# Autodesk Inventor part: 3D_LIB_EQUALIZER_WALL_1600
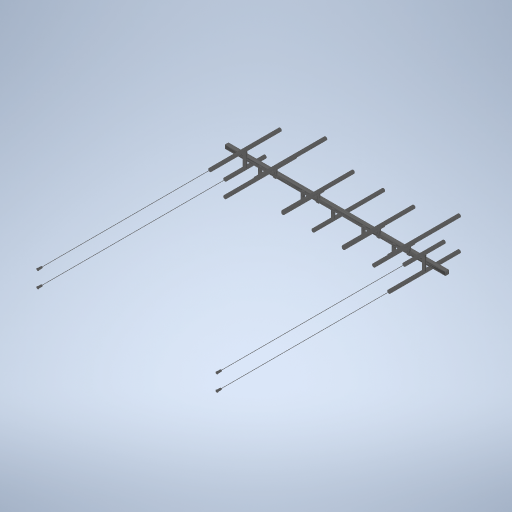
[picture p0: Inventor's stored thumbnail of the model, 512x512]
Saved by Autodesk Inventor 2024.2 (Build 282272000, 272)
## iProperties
Created: 2024-11
Part Number: 3D_LIB_EQUALIZER_WALL_1600
Material: Generic
Document SubType Name: Modeling
Designer: Stage
Density: 1 g/cm^3
Appearance: Default
Author: Stage
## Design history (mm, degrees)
node "456-4"
  node "MeshFeature1"
